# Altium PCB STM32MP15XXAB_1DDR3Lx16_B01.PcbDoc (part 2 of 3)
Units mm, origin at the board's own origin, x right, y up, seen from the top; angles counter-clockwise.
Board outline 86 x 120 mm, 4 copper layers (Top Layer, Signal Layer 1, Signal Layer 2, Bottom Layer), stack 1.571 mm thick; 144 components, 93 nets, 930 pads, 372 vias.
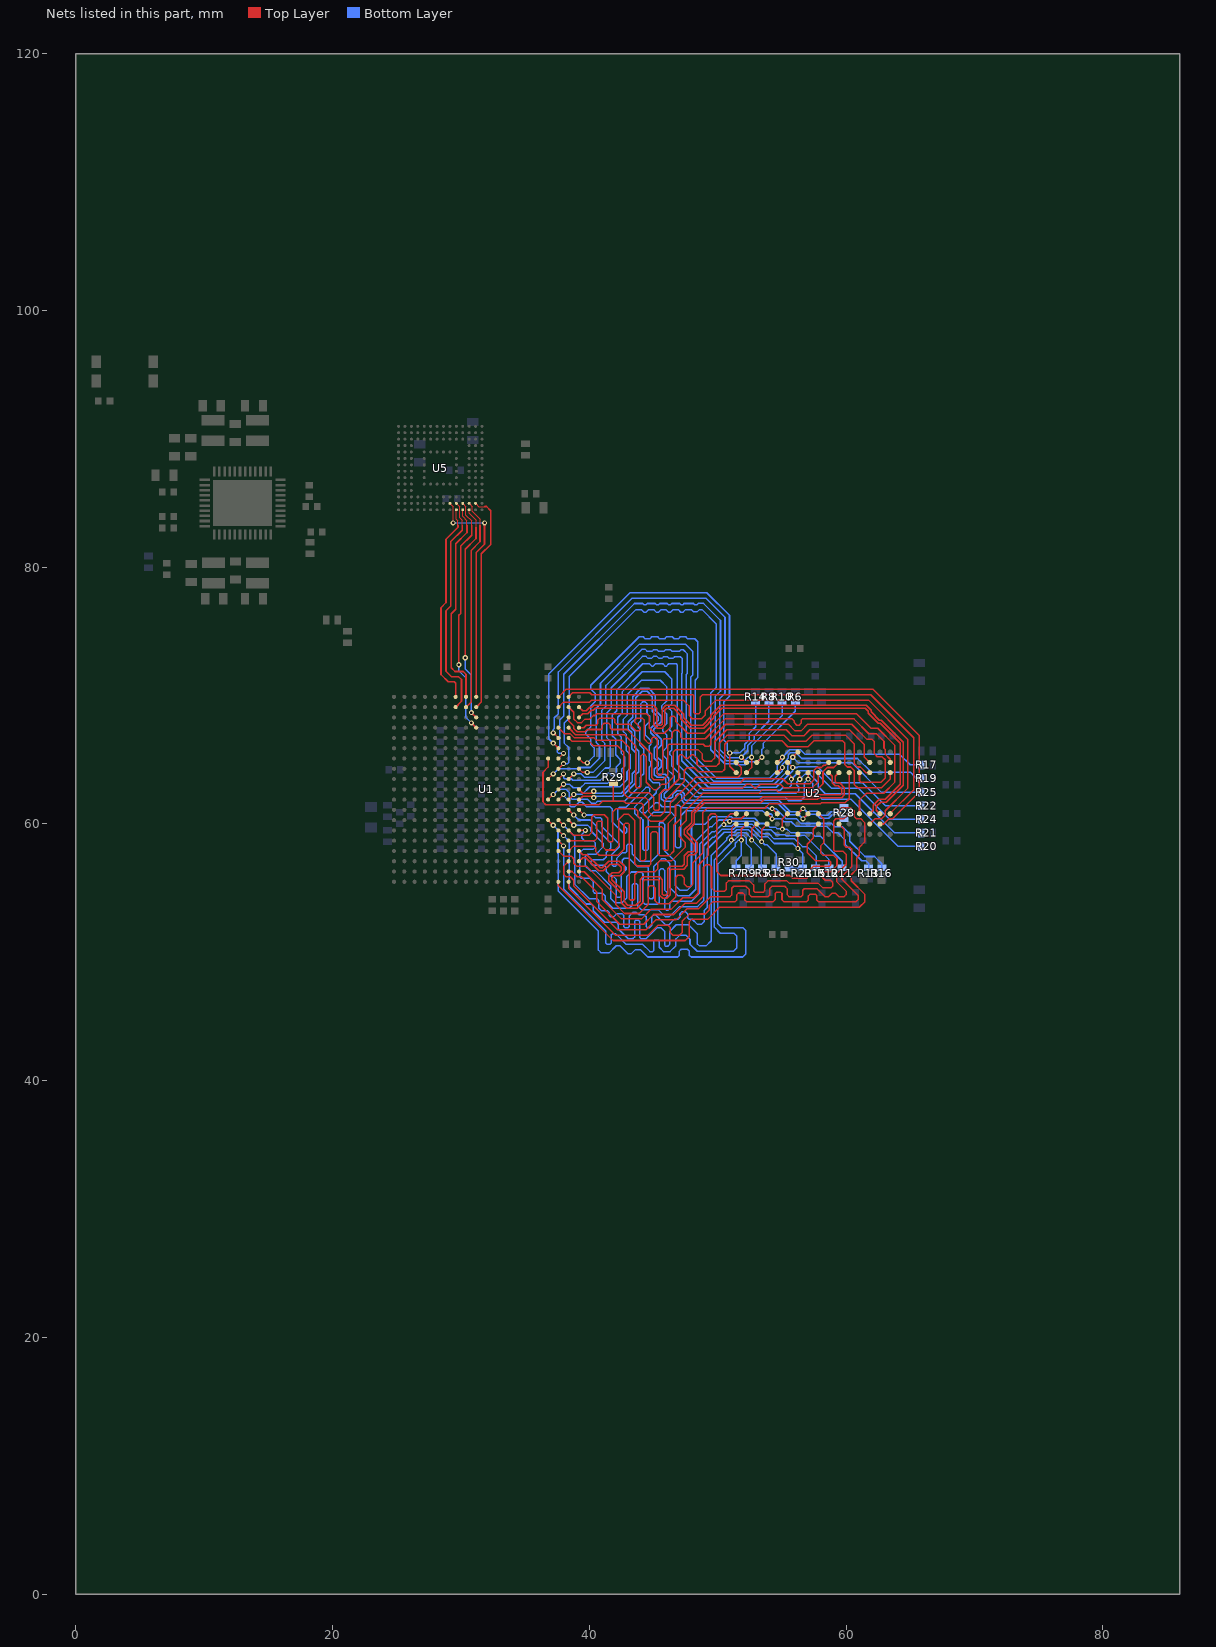
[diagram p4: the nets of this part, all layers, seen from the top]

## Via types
v1: diameter 0.4, hole 0.2, Top Layer to Bottom Layer, tented both sides, 309 vias
v2: diameter 0.6, hole 0.3, Top Layer to Bottom Layer, tented both sides, 61 vias
v3: diameter 0.4, hole 0.2, Top Layer to Signal Layer 1, tented top, 2 vias

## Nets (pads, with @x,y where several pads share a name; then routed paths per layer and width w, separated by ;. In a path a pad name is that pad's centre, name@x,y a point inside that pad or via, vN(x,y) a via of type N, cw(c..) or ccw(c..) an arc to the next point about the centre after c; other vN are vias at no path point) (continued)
DDR_A4: R5.1 U1.P17 U2.P8 | length 39.6
  Top Layer w0.12: U1.P17@37.6,59.5 v1(38,59.1) ; v1(52.65,58.75) 52.65,59.6 U2.P8@53.05,60
  Bottom Layer w0.12: v1(38,59.1) 38.44,58.66 38.44,55.117 39.787,53.77 40.16,53.77 40.32,53.61 40.32,53.237 41.217,52.34 42.13,52.34 42.27,52.2 42.27,51.836 43.046,51.06 43.39,51.06 43.53,51.2 43.53,52.41 43.615,52.495 43.845,52.495 43.95,52.39 43.95,51.16 44.05,51.06 44.43,51.06 45.304,51.934 45.574,51.934 45.869,51.639 45.869,50.571 45.96,50.48 46.12,50.48 46.29,50.65 46.29,51.648 46.786,52.144 47.732,52.144 48.43,51.446 48.43,50.65 48.58,50.5 49.1,50.5 49.5,50.9 49.5,57.55 50.71,58.76 50.71,58.899 50.921,59.11 51.37,59.11 51.59,59.33 52.19,59.33 52.65,58.87 v1(52.65,58.75) 52.679,58.75 53.41,58.019 53.41,56.7 R5.1@53.5,56.61
DDR_A5: R6.1 U1.H17 U2.P2 | length 43.5
  Top Layer w0.12: U1.H17@37.6,64.3 v1(38,64.7) ; U2.P2@53.05,64.8 v1(53.45,65.2)
  Bottom Layer w0.12: v1(38,64.7) 38.3,64.7 38.4,64.8 38.4,65.95 38.04,66.31 38.04,67.843 38.44,68.243 38.44,71.498 43.642,76.7 44.044,76.7 44.259,76.484 44.416,76.484 44.631,76.7 45.019,76.7 45.244,76.475 45.381,76.475 45.606,76.7 45.969,76.7 46.164,76.504 46.346,76.504 46.541,76.7 46.936,76.7 47.136,76.5 47.3,76.5 47.5,76.7 47.954,76.7 48.139,76.514 48.4,76.514 48.586,76.7 48.787,76.7 49.9,75.587 49.9,70.625 49.475,70.2 49.475,65.775 50.56,64.69 51.39,64.69 51.46,64.62 52.15,64.62 52.37,64.84 53.09,64.84 v1(53.45,65.2) 53.45,65.811 53.59,65.951 53.57,65.971 53.57,66.3 56.05,68.78 R6.1@56.05,69.45
DDR_A6: R7.1 U1.N16 U2.R8 | length 40.5
  Top Layer w0.12: U1.N16@36.8,60.3 v1(37.2,59.9) ; v1(51.85,58.75) 51.85,59.6 U2.R8@52.25,60
  Bottom Layer w0.12: v1(37.2,59.9) 37.57,59.53 37.57,57.69 37.6,57.66 37.6,54.769 40.719,51.65 40.719,50.181 40.94,49.96 41.54,49.96 42.099,50.519 42.399,50.519 43.008,49.91 43.29,49.91 43.6,50.22 43.976,50.22 44.556,49.64 45.114,49.64 46.89,49.64 47,49.75 47,50.075 47.175,50.25 47.64,50.25 47.79,50.1 47.79,49.785 47.935,49.64 51.965,49.64 52.2,49.875 52.2,51.7 51.975,51.925 50.335,51.925 50.025,52.235 50.025,56.887 51.088,57.95 51.088,57.957 51.381,58.25 51.381,58.499 51.632,58.75 v1(51.85,58.75) 51.85,57.54 51.45,57.14 R7.1@51.45,56.61
DDR_A7: R8.1 U1.E17 U2.R2 | length 39.6
  Top Layer w0.12: v1(37.2,67.1) U1.E17@37.6,66.7 ; v1(51.85,65.2) U2.R2@52.25,64.8
  Bottom Layer w0.12: v1(37.2,67.1) 37.2,67.35 37.28,67.43 37.28,68.271 37.6,68.591 37.6,71.846 43.352,77.598 49.077,77.598 50.575,76.1 50.575,70.175 50.15,69.75 50.15,65.821 50.801,65.17 51.82,65.17 v1(51.85,65.2) 52.35,65.7 52.35,66.109 52.87,66.629 52.87,66.883 53.99,68.003 R8.1@53.99,69.45
DDR_A8: R9.1 U1.R17 U2.T8 | length 39.7
  Top Layer w0.12: U1.R17@37.6,58.7 v1(38,58.3) ; v1@51.09,58.77 51.09,59.64 U2.T8@51.45,60
  Bottom Layer w0.12: v1(38,58.3) 38.02,58.28 38.02,54.943 41.29,51.673 41.29,50.73 41.39,50.63 41.6,50.63 41.71,50.74 41.71,51.37 41.81,51.47 42.042,51.47 42.872,50.64 44.15,50.64 44.73,50.06 44.94,50.06 45.03,50.15 45.03,50.88 45.1,50.95 45.374,50.95 45.449,50.875 45.449,50.397 45.786,50.06 46.294,50.06 46.753,50.519 46.753,51.053 47.025,51.325 47.55,51.325 47.85,51.025 47.85,50.636 48.406,50.08 51.23,50.08 51.5,50.35 51.5,51.275 51.275,51.5 50.2,51.5 49.75,51.95 49.75,57.213 51.07,58.533 v1(51.07,58.75) ; v1@51.11,58.75 51.321,58.75 51.681,59.11 52.02,59.11 52.22,58.91 52.22,58.48 52.61,58.09 52.61,56.74 R9.1@52.48,56.61
DDR_A9: R10.1 U1.G17 U2.R3 | length 43
  Top Layer w0.12: U1.G17@37.6,65.1 v1(38,65.5) ; U2.R3@52.25,64 52.65,64.4 v1(52.65,65.2)
  Bottom Layer w0.12: v1(38,65.5) 37.625,65.5 37.525,65.6 37.525,65.775 37.7,65.95 37.7,68.097 38.02,68.417 38.02,71.672 43.523,77.175 44.163,77.175 44.263,77.075 44.412,77.075 44.512,77.175 45.138,77.175 45.238,77.075 45.387,77.075 45.487,77.175 46.088,77.175 46.188,77.075 46.322,77.075 46.422,77.175 47.055,77.175 47.155,77.075 47.281,77.075 47.381,77.175 48.125,77.175 48.225,77.075 48.39,77.075 48.493,77.178 48.903,77.178 50.225,75.856 50.225,70.35 49.8,69.925 49.8,65.831 50.701,64.93 51.59,64.93 51.68,64.84 52,64.84 52.36,65.2 v1(52.65,65.2) 52.65,66.069 55.02,68.439 R10.1@55.02,69.45
DDR_A10: R11.1 U1.M19 U2.L7 | length 42.3
  Top Layer w0.12: U1.M19@39.22,61.1 U1.M19@39.2,61.1 v1(39.6,60.7) ; v1(55.05,59.6) 55.05,60.4 U2.L7@55.45,60.8
  Bottom Layer w0.12: v1(39.6,60.7) 40.282,60.7 40.482,60.5 40.875,60.5 40.96,60.415 40.96,59.816 42.34,58.436 42.34,58.2 41.74,57.6 41.74,56.85 41.865,56.725 42.05,56.725 42.15,56.825 42.16,56.825 42.16,57.344 42.56,57.744 42.814,57.744 42.93,57.86 42.93,58.33 43.04,58.44 43.24,58.44 43.35,58.33 43.35,57.673 43.923,57.101 44.848,57.101 45.45,57.703 45.45,60.04 45.5,60.09 45.74,60.09 45.87,59.96 45.87,57.922 46.71,57.082 46.71,55.212 47.094,54.828 47.618,54.828 47.966,55.176 47.966,59.791 48.15,59.975 49.025,59.975 49.61,60.56 50.91,60.56 51.089,60.56 51.199,60.45 52.89,60.45 53.3,60.04 53.79,60.04 54.067,59.763 54.5,59.763 54.62,59.643 55.007,59.643 v1(55.05,59.6) 55.41,59.6 55.68,59.33 57.29,59.33 57.56,59.06 57.999,59.06 58.26,58.799 58.26,58.53 59.7,57.09 R11.1@59.7,56.61
DDR_A11: R12.1 U1.M18 U2.R7 | length 46.6
  Top Layer w0.12: U1.M18@38.4,61.1 v1(38.8,60.7) ; v1@50.94,60.21 51.13,60.4 51.85,60.4 U2.R7@52.25,60.8
  Bottom Layer w0.12: v1(38.8,60.7) 39.19,60.31 40.078,60.31 40.54,59.848 40.54,59.642 41.688,58.494 41.688,58.142 41.32,57.774 41.32,57.43 41.1,57.21 40.25,57.21 40.12,57.08 40.12,56.92 40.25,56.79 41.16,56.79 41.16,56.78 41.31,56.63 41.31,56.316 41.676,55.95 41.85,55.95 42.09,55.71 42.09,54.38 42.19,54.28 42.37,54.28 42.51,54.42 42.51,56.079 42.866,56.434 42.866,56.624 42.58,56.91 42.58,57.17 42.734,57.324 43.105,57.324 43.749,56.681 44.5,56.681 44.61,56.571 44.61,54.29 44.725,54.175 44.915,54.175 45.03,54.29 45.03,56.689 45.625,57.284 45.914,57.284 46.29,56.908 46.29,55.038 46.92,54.408 47.792,54.408 48.3,54.916 48.3,58.675 49.424,59.799 49.569,59.799 50.08,60.31 50.84,60.31 50.94,60.21 52.79,60.21 53.457,59.543 54.177,59.543 54.56,59.16 55.24,59.16 55.32,59.08 56.471,59.08 56.501,59.11 56.799,59.11 58.67,57.239 R12.1@58.67,56.61
  other v1: 50.94,60.2
DDR_A12: R13.1 U1.L17 U2.N7 | length 47.2
  Top Layer w0.12: U1.L17@37.6,61.9 v1(38,62.3) ; U2.N7@53.85,60.8 v1(54.25,60.4)
  Bottom Layer w0.12: v1(38,62.3) 38,62.23 38.49,61.74 38.49,61.42 38.58,61.33 38.85,61.33 39.21,61.69 39.45,61.69 39.81,61.33 41.64,61.33 41.8,61.17 41.8,60.164 42.684,59.28 42.82,59.28 42.93,59.39 42.93,59.646 42.22,60.356 42.22,61.16 42.38,61.32 42.889,61.32 44.419,62.85 44.625,62.85 44.725,62.75 44.725,62.525 43.53,61.33 43.53,60.846 43.906,60.47 44.04,60.47 44.19,60.32 44.19,58.021 44.271,57.941 44.5,57.941 44.61,58.051 44.61,60.516 45.024,60.93 46.37,60.93 46.71,60.59 46.71,58.27 46.84,58.14 47.006,58.14 47.126,58.26 47.126,60.646 47.52,61.04 53.5,61.04 53.76,60.78 54.17,60.78 54.25,60.7 v1(54.25,60.4) 54.931,60.4 55.151,60.18 55.74,60.18 56.1,59.82 58.49,59.82 58.975,59.335 59.355,59.335 59.93,58.76 59.93,58.43 61.22,57.14 61.56,57.14 61.76,56.94 R13.1@61.76,56.61
DDR_A13: R14.1 U1.F17 U2.T3 | length 41.6
  Top Layer w0.12: v1(37.2,66.3) U1.F17@37.6,65.9 ; v1(50.95,65.53) 50.95,64.5 U2.T3@51.45,64
  Bottom Layer w0.12: v1@37.2,66.28 37.19,66.29 36.84,66.64 36.84,71.68 43.178,78.018 49.157,78.018 50.925,76.25 50.925,69.95 50.485,69.51 50.485,66.535 50.74,66.28 50.74,65.74 v1(50.95,65.53) 51.18,65.53 51.21,65.56 51.77,65.56 52.11,65.9 52.11,66.208 52.45,66.548 52.45,67.057 52.97,67.577 R14.1@52.97,69.45
DDR_A14: R15.1 U1.N18 U2.T7 | length 45
  Top Layer w0.12: U1.N18@38.4,60.3 v1(38.8,59.9) ; v1(50.49,59.95) 50.49,60.28 51.01,60.8 U2.T7@51.45,60.8
  Bottom Layer w0.12: v1(38.8,59.9) 38.81,59.89 39.904,59.89 40.12,59.674 40.12,59.468 41.084,58.504 41.084,58.21 40.504,57.63 39.854,57.63 39.7,57.476 39.7,56.746 40.076,56.37 40.48,56.37 41.67,55.18 41.67,54.206 42.016,53.86 42.544,53.86 42.93,54.246 42.93,55.905 43.286,56.261 44.059,56.261 44.19,56.13 44.19,53.9 44.335,53.755 45.325,53.755 45.45,53.88 45.45,56.375 45.575,56.5 45.75,56.5 45.87,56.38 45.87,54.864 46.07,54.664 46.07,54.36 45.87,54.16 45.87,53.42 46.02,53.27 46.13,53.27 46.29,53.43 46.29,53.876 46.402,53.988 47.966,53.988 48.625,54.647 48.625,58.465 49.539,59.379 49.749,59.379 50.32,59.95 v1(50.49,59.95) 50.5,59.95 50.62,59.83 51.089,59.83 51.249,59.99 52.68,59.99 53.43,59.24 53.997,59.24 54.397,58.84 56.009,58.84 56.61,58.239 56.971,58.239 57.67,57.54 57.67,56.64 R15.1@57.64,56.61
DDR_A15: R16.1 U1.L16 U2.M7 | length 48.7
  Top Layer w0.12: U1.L16@36.8,61.9 v1(37.2,62.3) ; v1(54.25,61.2) U2.M7@54.65,60.8
  Bottom Layer w0.12: v1(37.2,62.3) 37.6,62.7 38.19,62.7 38.44,62.45 38.44,62.151 38.651,61.94 39.849,61.94 40.189,61.6 40.48,61.6 40.65,61.77 42.745,61.77 43.994,63.019 43.994,63.651 44.25,63.907 44.25,65.832 43.95,66.132 43.95,67.402 43.81,67.542 43.81,67.825 44.03,68.045 44.03,69.38 44.175,69.525 44.35,69.525 44.5,69.375 44.5,68.62 44.7,68.42 44.7,67.965 44.37,67.635 44.37,66.925 44.81,66.485 44.81,66.22 44.67,66.08 44.67,64.95 44.795,64.825 44.795,64.55 44.67,64.425 44.67,63.52 44.97,63.22 45.419,63.22 45.509,63.13 45.509,62.904 45.22,62.615 45.22,62.426 43.95,61.156 43.95,61.02 44.08,60.89 44.39,60.89 45.16,61.66 45.375,61.66 45.685,61.35 46.635,61.35 46.755,61.47 46.98,61.47 47.17,61.28 53.9,61.28 53.98,61.2 v1(54.25,61.2) 54.52,61.2 55.32,60.4 56.141,60.4 56.501,60.04 58.88,60.04 59.13,59.79 59.73,59.79 60.29,59.23 60.29,58.651 61.471,57.47 62.22,57.47 62.79,56.9 R16.1@62.79,56.61
DDR_BA0: R17.1 U1.G19 U2.M2 | length 47.9
  Top Layer w0.12: U1.G19@39.2,65.1 39.54,64.76 v1(39.85,64.76) ; U2.M2@54.65,64.8 v1(55.05,65.2)
  Bottom Layer w0.12: v1(39.85,64.76) 40.38,65.29 40.38,65.923 40.12,66.183 40.12,66.626 39.72,67.026 39.72,67.147 40.12,67.547 40.12,69.184 40.46,69.524 40.46,70.184 40.12,70.524 40.12,70.802 43.893,74.575 44.209,74.575 44.35,74.434 44.725,74.434 44.866,74.575 45.334,74.575 45.475,74.434 45.875,74.434 46.016,74.575 46.475,74.575 46.616,74.434 46.95,74.434 47.091,74.575 47.51,74.575 47.66,74.425 48.225,74.425 48.45,74.2 48.45,71.4 48.25,71.2 48.25,65.225 49.895,63.58 54.059,63.58 54.64,64.161 54.64,64.551 55.05,64.961 v1(55.05,65.2) 55.27,65.42 55.27,65.44 55.61,65.78 55.63,65.78 55.64,65.79 56.46,65.79 56.83,65.42 64.19,65.42 65,64.61 R17.1@65.85,64.61
DDR_BA1: R18.1 U1.N17 U2.N8 | length 37.7
  Top Layer w0.12: U1.N17@37.6,60.3 v1(38,59.9) ; v1@53.43,58.639 53.43,59.58 U2.N8@53.85,60
  Bottom Layer w0.12: v1(38,59.9) 38.86,59.04 38.86,55.331 40.001,54.19 40.6,54.19 40.74,54.05 40.74,53.451 40.935,53.255 41.433,53.255 41.545,53.143 41.545,52.88 41.665,52.76 41.9,52.76 42.16,53.02 42.55,53.02 42.69,52.88 42.69,52.01 42.79,51.91 43.002,51.91 43.11,52.018 43.11,52.836 43.412,53.138 43.648,53.138 43.871,52.915 44.295,52.915 44.44,52.77 44.44,52.02 44.55,51.91 44.686,51.91 44.86,52.084 44.86,52.755 45.02,52.915 45.187,52.915 45.962,52.14 46.188,52.14 46.612,52.564 46.914,52.564 47.07,52.72 47.07,53.022 47.196,53.148 47.525,53.148 47.675,52.998 47.675,52.689 47.789,52.575 48.025,52.575 48.425,52.175 48.725,52.175 48.975,52.425 48.975,53.275 49.2,53.5 49.2,58.025 50.525,59.35 51.299,59.35 51.499,59.55 52.411,59.55 53.331,58.63 v1(53.43,58.63) 53.67,58.39 53.839,58.39 54.56,57.669 54.56,56.64 R18.1@54.53,56.61
DDR_BA2: R19.1 U1.J16 U2.M3 | length 49.3
  Top Layer w0.12: U1.J16@36.8,63.5 v1(37.2,63.9) v1@37.21,63.91 ; U2.M3@54.65,64 v1@55.03,64.38
  Bottom Layer w0.12: v1(37.2,63.9) 37.6,64.3 39.1,64.3 39.2,64.4 40.084,64.4 40.8,65.116 40.8,66.097 40.54,66.357 40.54,69.01 40.88,69.35 40.88,70.968 43.926,74.014 47.477,74.014 48.075,73.416 48.075,71.625 47.925,71.475 47.925,65.075 49.66,63.34 54.25,63.34 55.05,64.14 v1(55.05,64.4) 55.05,64.65 55.44,65.04 55.44,65.089 55.49,65.139 55.49,65.349 55.701,65.56 56.09,65.56 56.55,65.1 60.9,65.1 61.96,64.04 65.01,64.04 65.48,63.57 R19.1@65.85,63.57
DDR_CASN: R21.1 U1.K17 U2.K3 | length 49.1
  Top Layer w0.12: U1.K17@37.6,62.7 37.61,62.7 v1@38.005,63.095 ; U2.K3@56.25,64 56.25,63.92 56.4,63.77 v1(56.4,63.49)
  Bottom Layer w0.12: v1@38.02,63.08 v1(38,63.1) 38.47,63.1 38.75,62.82 39.33,62.82 39.67,63.16 41.424,63.16 41.594,63.33 42.226,63.33 42.524,63.628 42.524,64.26 42.78,64.516 42.78,65.223 42.48,65.523 42.48,66.793 42.22,67.053 42.22,68.314 42.56,68.654 42.56,70.272 44.138,71.85 45.875,71.85 46.445,71.28 46.445,69.391 46.2,69.146 46.2,69.01 46.445,68.764 46.445,67.631 46.28,67.465 46.28,67.3 46.445,67.134 46.445,65.776 46.28,65.61 46.28,65.42 46.445,65.254 46.445,64.501 47.039,63.908 47.039,63.62 47.15,63.509 47.438,63.509 48.566,62.38 56.1,62.38 56.33,62.61 56.33,62.87 56.17,63.03 56.17,63.21 56.17,63.26 v1(56.4,63.49) 56.77,63.86 57.199,63.86 57.84,63.219 57.84,62.91 58.39,62.36 ; 58.34,62.4 58.38,62.36 58.39,62.36 ; R21.1@65.85,59.31 63.77,59.31 60.72,62.36 58.39,62.36
DDR_CKE: R23.1 R30.2 U1.P19 U2.K9 | length 38.3
  Top Layer w0.12: U1.P19@39.2,59.5 v1(39.7,59.5) ; v1(56.25,58.09) U2.K9@56.25,59.2
  Bottom Layer w0.12: v1(39.7,59.5) 39.7,59.47 39.41,59.18 39.41,58.92 39.64,58.69 40.3,58.69 40.302,58.692 40.48,58.514 40.48,58.2 40.33,58.05 39.56,58.05 39.28,57.77 39.28,55.86 39.37,55.77 40.055,55.77 40.3,55.525 40.3,54.74 40.43,54.61 41.03,54.61 41.25,54.39 41.25,54.032 41.842,53.44 43.12,53.44 43.35,53.67 43.35,55.25 43.45,55.35 43.675,55.35 43.77,55.255 43.77,53.61 44.045,53.335 45.361,53.335 45.936,52.76 46.214,52.76 47.022,53.568 48.444,53.568 48.925,54.049 48.925,58.3 49.6,58.975 49.729,58.975 50.341,59.587 50.341,59.59 51.16,59.59 51.228,59.59 51.408,59.77 52.54,59.77 53.29,59.02 53.88,59.02 54.42,58.48 55.86,58.48 v1(56.25,58.09) 56.64,57.7 56.64,56.64 R23.1@56.61,56.61 56.57,56.57 R30.2@55.57,56.57
DDR_CLK_N: R28.1 U1.K19 U2.K7 | length 40.4
  Top Layer w0.1: U1.K19@39.2,62.7 39.49,62.41 40.21,62.41 v1(40.35,62.55) ; U2.K7@56.25,60.8 v1(56.65,61.2)
  Bottom Layer w0.1: v1(40.35,62.55) 40.49,62.41 42.48,62.41 43.354,63.284 43.354,63.916 43.61,64.172 43.61,65.567 43.31,65.867 43.31,67.137 43.05,67.397 43.05,67.97 43.39,68.31 43.39,69.915 44.031,70.556 44.619,70.556 45.158,70.017 45.158,68.868 45.615,68.41 45.615,67.975 45.01,67.37 45.01,67.19 45.615,66.585 45.615,66.12 45.31,65.815 45.31,65.215 45.615,64.91 45.615,64.455 45.31,64.15 45.31,63.95 45.4,63.86 45.913,63.86 46.209,63.564 46.209,62.699 45.86,62.35 45.86,62.08 45.95,61.99 46.37,61.99 46.52,62.14 46.52,62.305 46.813,62.599 47.174,62.599 47.42,62.353 47.42,61.935 47.505,61.85 54.775,61.85 55.665,60.96 56.41,60.96 v1(56.65,61.2) 56.7,61.2 56.94,60.96 57.145,60.96 57.175,60.99 57.755,60.99 58.075,60.67 58.56,60.67 58.86,60.97 59.5,60.97 R28.1@59.85,61.32
DDR_CLK_P: R28.2 U1.L19 U2.J7 | length 40.4
  Top Layer w0.1: U1.L19@39.2,61.9 39.48,62.18 40.22,62.18 v1(40.35,62.05) ; v1(56.65,60.4) U2.J7@57.05,60.8
  Bottom Layer w0.1: v1(40.35,62.05) 40.48,62.18 42.575,62.18 43.584,63.189 43.584,63.821 43.84,64.077 43.84,65.662 43.54,65.962 43.54,67.232 43.28,67.492 43.28,67.875 43.62,68.215 43.62,69.82 44.126,70.326 44.524,70.326 44.928,69.922 44.928,68.772 45.385,68.315 45.385,68.07 44.78,67.465 44.78,67.095 45.385,66.49 45.385,66.215 45.08,65.91 45.08,65.12 45.385,64.815 45.385,64.55 45.08,64.245 45.08,63.855 45.305,63.63 45.817,63.63 45.979,63.469 45.979,62.794 45.63,62.445 45.63,61.985 45.855,61.76 46.465,61.76 46.75,62.045 46.75,62.21 46.909,62.369 47.079,62.369 47.19,62.257 47.19,61.84 47.41,61.62 54.68,61.62 55.57,60.73 56.317,60.73 v1@56.605,60.443 ; v1(56.65,60.4) 56.98,60.73 57.24,60.73 57.27,60.76 57.66,60.76 57.98,60.44 58.655,60.44 58.955,60.74 59.53,60.74 R28.2@59.85,60.42
DDR_CSN: R22.1 U1.J18 U2.L2 | length 47.3
  Top Layer w0.12: U1.J18@38.4,63.5 v1(38.8,63.9) ; U2.L2@55.45,64.8 v1(55.85,64.4)
  Bottom Layer w0.12: v1(38.8,63.9) 39.389,63.9 39.639,63.65 40.522,63.65 41.232,64.36 41.535,64.36 41.64,64.465 41.64,66.445 41.38,66.705 41.38,68.662 41.72,69.002 41.72,70.62 44.15,73.05 44.425,73.05 44.425,73.045 44.575,72.895 44.845,72.895 45,73.05 45.275,73.05 45.43,72.895 45.67,72.895 45.813,73.038 46.082,73.038 46.225,72.895 46.52,72.895 46.66,73.035 47.095,73.035 47.25,72.88 47.25,71.775 47.2,71.725 47.2,64.934 49.274,62.86 54.57,62.86 55.85,64.14 v1(55.85,64.4) 56.197,64.4 56.257,64.46 57.787,64.46 59.047,63.2 61.3,63.2 63.07,61.43 R22.1@65.85,61.43
DDR_DQ0: U1.A17 U2.B8 | length 38.3
  Top Layer w0.12: U1.A17@37.6,69.9 38.19,70.49 62.112,70.49 65.7,66.902 65.7,62.487 63.618,60.405 63.345,60.405 62.94,60 U2.B8@62.65,60
DDR_DQ1: U1.A18 U2.A7 | length 37.8
  Top Layer w0.12: U1.A18@38.4,69.9 38.4,69.92 38.7,70.22 40.041,70.22 40.191,70.07 48.08,70.07 48.15,70 48.15,68.675 48.225,68.6 48.55,68.6 48.65,68.7 48.65,69.9 48.82,70.07 61.93,70.07 65.275,66.725 65.275,62.656 U2.A7@63.47,60.851
DDR_DQ2: U1.D18 U2.C2 | length 38.9
  Top Layer w0.12: U1.D18@38.4,67.5 38.96,66.94 42.768,66.94 43.61,66.098 43.61,62.915 43.7,62.825 43.925,62.825 44.03,62.93 44.03,65.304 44.15,65.424 44.284,65.424 44.45,65.258 44.45,63.244 45.044,62.65 45.21,62.65 45.64,63.08 45.978,63.08 46.55,63.652 46.55,65.61 46.74,65.8 48.47,65.8 48.814,65.456 48.814,65.05 48.964,64.9 49.525,64.9 49.775,65.15 49.775,66.4 50.715,67.34 55.339,67.34 55.819,66.86 56.701,66.86 57.181,67.34 60.279,67.34 61.41,66.209 61.41,65.24 U2.C2@61.85,64.8
DDR_DQ3: U1.B17 U2.C8 | length 38.6
  Top Layer w0.12: U1.B17@37.6,69.1 38,69.5 40.041,69.5 40.191,69.65 47.325,69.65 47.78,69.195 47.78,68.445 48.025,68.2 48.75,68.2 49.05,68.5 49.05,68.825 49.875,69.65 61.75,69.65 64.8,66.6 64.8,62.775 63.05,61.025 63.05,60.691 62.759,60.4 62.25,60.4 U2.C8@61.85,60
DDR_DQ4: U1.E18 U2.A3 | length 39
  Top Layer w0.12: U1.E18@38.4,66.7 38.64,66.46 39.974,66.46 40.334,66.1 42.2,66.1 42.69,65.61 42.69,62.374 43.034,62.03 44.416,62.03 44.62,61.826 44.62,60.976 44.956,60.64 45.554,60.64 45.88,60.966 45.88,61.794 47.4,63.314 47.4,64.15 47.625,64.375 48.175,64.375 48.49,64.06 50.34,64.06 50.55,64.27 50.55,66.21 50.82,66.48 55.011,66.48 55.471,66.02 57.049,66.02 57.509,66.48 59.73,66.48 59.89,66.32 59.89,64.651 60.101,64.44 60.37,64.44 60.65,64.16 60.65,63.08 60.91,62.82 62.766,62.82 63.45,63.504 U2.A3@63.45,64
DDR_DQ5: U1.D17 U2.C3 | length 38.2
  Top Layer w0.12: U1.D17@37.6,67.5 38.06,67.04 38.513,67.04 38.853,66.7 40.38,66.7 40.56,66.52 42.555,66.52 43.11,65.965 43.11,62.548 43.208,62.45 44.63,62.45 45.04,62.04 45.04,61.15 45.13,61.06 45.38,61.06 45.46,61.14 45.46,62.306 45.814,62.66 46.152,62.66 46.97,63.478 46.97,65.28 47.07,65.38 47.26,65.38 47.52,65.12 47.69,65.12 47.95,65.38 48.148,65.38 48.394,65.134 48.394,64.67 48.584,64.48 49.87,64.48 50.12,64.73 50.12,66.295 50.725,66.9 55.185,66.9 55.645,66.44 56.875,66.44 57.335,66.9 59.99,66.9 60.65,66.24 60.65,64.691 60.901,64.44 61.119,64.44 61.559,64 U2.C3@61.85,64
DDR_DQ6: U1.D19 U2.A2 | length 38.5
  Top Layer w0.12: U1.D19@39.2,67.5 39.57,67.5 39.77,67.7 40.55,67.7 40.675,67.825 40.675,68.1 40.825,68.25 41.875,68.25 42,68.125 42,67.9 42.125,67.775 43.134,67.775 43.65,67.259 43.884,67.259 43.975,67.35 43.975,67.525 43.55,67.95 43.55,68.1 43.675,68.225 44.15,68.225 44.3,68.075 44.3,66.6 44.625,66.275 44.775,66.275 44.875,66.375 44.875,66.65 44.975,66.75 45.2,66.75 45.29,66.66 45.29,63.935 45.425,63.8 45.575,63.8 45.71,63.935 45.71,66.51 45.84,66.64 46.34,66.64 46.457,66.757 46.457,67.107 46.65,67.3 46.9,67.3 47.12,67.08 47.12,66.78 47.26,66.64 49.04,66.64 50.58,68.18 55.82,68.18 55.97,68.03 55.97,67.897 56.167,67.7 56.353,67.7 56.5,67.847 56.5,68.08 56.6,68.18 60.628,68.18 61.778,67.03 62.37,67.03 62.96,66.44 62.96,65.89 63.04,65.81 63.04,65.46 63.45,65.05 U2.A2@63.45,64.8
DDR_DQ7: U1.B18 U2.D7 | length 38.3
  Top Layer w0.12: U1.B18@38.4,69.1 38.8,68.7 38.8,68.18 39.08,67.9 39.4,67.9 39.67,68.17 40.045,68.17 40.325,68.45 40.476,68.45 40.626,68.6 44.44,68.6 44.675,68.365 44.675,67.505 45.12,67.06 45.85,67.06 46.31,67.52 46.31,68.285 46.425,68.4 46.6,68.4 46.73,68.27 46.73,68.011 47.681,67.06 48.96,67.06 50.5,68.6 60.802,68.6 61.952,67.45 62.479,67.45 63.81,66.119 63.81,63.27 62.94,62.4 61.59,62.4 61.05,61.86 U2.D7@61.05,60.8
DDR_DQ8: U1.P18 U2.G2 | length 39.3
  Top Layer w0.12: U1.P18@38.4,59.5 38.79,59.11 39.96,59.11 40.18,59.33 40.18,60.53 40.375,60.725 41.175,60.725 41.45,60.45 41.45,58.725 41.55,58.625 41.775,58.625 41.85,58.7 41.85,60.95 42.09,61.19 43.61,61.19 43.78,61.02 43.78,60.628 43.97,60.438 43.97,57.22 44.04,57.15 44.28,57.15 44.39,57.26 44.39,59.67 44.52,59.8 45.62,59.8 45.75,59.67 45.75,58.07 45.86,57.96 46.07,57.96 46.17,58.06 46.17,60.068 46.72,60.618 46.72,61.446 48.494,63.22 51.773,63.22 52.073,63.52 55.08,63.52 55.47,63.13 57.189,63.13 57.49,63.431 57.49,64.16 57.73,64.4 58.09,64.4 58.26,64.57 58.4,64.57 58.63,64.8 U2.G2@58.65,64.8
DDR_DQ9: U1.T17 U2.E3 | length 38.3
  Top Layer w0.12: U1.T17@37.6,57.9 38,57.5 38.6,57.5 38.8,57.3 38.8,56.94 39.04,56.7 39.82,56.7 42.08,54.44 42.08,53.705 42.755,53.03 43.895,53.03 44.6,53.735 44.6,55.06 44.72,55.18 44.995,55.18 45.125,55.05 45.125,54.025 45.357,53.793 46.228,53.793 46.74,54.305 46.74,55.84 46.9,56 47.2,56 47.4,55.8 47.4,55.325 47.6,55.125 47.875,55.125 48.075,55.325 48.075,56.985 48.84,57.75 48.84,60.893 49.167,61.22 53.67,61.22 54.01,61.56 58.005,61.56 58.095,61.65 59.925,61.65 60.25,61.975 U2.E3@60.25,64
DDR_DQ10: U1.R18 U2.H3 | length 38.3
  Top Layer w0.12: U1.R18@38.4,58.7 40.42,58.7 40.6,58.88 40.6,60.15 40.675,60.225 40.95,60.225 41.03,60.145 41.03,58.245 41.3,57.975 41.975,57.975 42.29,58.29 42.29,60.326 42.734,60.77 43.044,60.77 43.55,60.264 43.55,56.91 43.73,56.73 44.66,56.73 44.81,56.88 44.81,59.286 44.904,59.38 45.23,59.38 45.33,59.28 45.33,57.71 45.5,57.54 46.244,57.54 46.59,57.886 46.59,59.894 47.14,60.444 47.14,61.272 48.668,62.8 51.947,62.8 52.247,63.1 52.56,63.1 52.86,62.8 53.016,62.8 53.316,63.1 54.906,63.1 55.196,62.81 57.361,62.81 57.85,63.299 U2.H3@57.85,64
DDR_DQ11: U1.V19 U2.H8 | length 38.3
  Top Layer w0.12: U1.V19@39.2,56.28 39.62,56.28 41.025,54.875 41.025,54.1 42.515,52.61 44.069,52.61 44.832,53.373 46.402,53.373 47.279,54.25 48.15,54.25 48.5,54.6 48.5,56.79 49.26,57.55 49.26,60.546 49.514,60.8 49.775,60.8 49.92,60.655 49.92,56.318 50.248,55.99 55.599,55.99 55.799,55.79 56.97,55.79 57.22,56.04 57.22,56.47 57.46,56.71 58.71,56.71 58.812,56.812 58.812,57.025 58.702,57.136 57.614,57.136 56.98,57.77 56.98,58.43 57.45,58.9 57.45,59.6 U2.H8@57.85,60
DDR_DQ12: U1.W18 U2.F8 | length 37.7
  Top Layer w0.12: U1.W18@38.4,55.5 38.4,54.977 42.027,51.35 44.591,51.35 45.353,52.113 46.137,52.113 46.3,51.95 46.3,51.563 46.513,51.35 47.05,51.35 47.25,51.55 47.25,52.439 47.801,52.99 49.036,52.99 49.335,53.29 49.335,53.66 49.605,53.93 51.35,53.93 51.475,54.055 51.475,54.475 51.625,54.625 51.975,54.625 52.125,54.475 52.125,54.075 52.27,53.93 54.31,53.93 54.474,54.094 54.474,54.574 54.6,54.7 54.9,54.7 55.014,54.586 55.014,54.096 55.18,53.93 56.9,53.93 57.075,54.105 57.075,54.4 57.205,54.53 57.62,54.53 57.726,54.424 57.726,54.074 57.87,53.93 60.766,53.93 60.94,54.104 60.94,54.444 59.69,55.694 59.69,55.93 60.43,56.67 60.43,58.06 60.295,58.195 60.015,58.195 59.85,58.36 59.85,59.6 U2.F8@59.45,60
DDR_DQ13: U1.T18 U2.F2 | length 38.3
  Top Layer w0.12: U1.T18@38.4,57.9 38.78,58.28 40.36,58.28 40.525,58.115 40.525,57.825 40.775,57.575 42.25,57.575 42.71,58.035 42.71,59.96 42.825,60.075 43.025,60.075 43.13,59.97 43.13,54.14 43.19,54.08 43.46,54.08 43.55,54.17 43.55,56.04 43.8,56.29 45.125,56.29 45.35,56.515 45.35,56.975 45.495,57.12 46.418,57.12 47.47,58.172 47.47,58.58 47.01,59.04 47.01,59.72 47.56,60.27 47.56,61.098 48.842,62.38 53.19,62.38 53.49,62.68 54.54,62.68 54.73,62.49 57.57,62.49 58.21,63.13 58.21,64.069 58.541,64.4 59.05,64.4 U2.F2@59.45,64.8
DDR_DQ14: U1.V18 U2.H7 | length 38.3
  Top Layer w0.12: U1.V18@38.4,56.3 38.66,56.3 39.06,55.9 39.406,55.9 40.596,54.71 40.596,53.969 42.375,52.19 44.243,52.19 45.005,52.953 46.576,52.953 47.453,53.83 48.355,53.83 48.9,54.375 48.9,56.625 49.1,56.825 49.375,56.825 49.525,56.675 49.525,55.025 49.8,54.75 50.525,54.75 50.675,54.9 50.675,55.395 50.85,55.57 52.48,55.57 52.8,55.25 52.8,54.8 52.9,54.7 53.575,54.7 53.675,54.8 53.675,55.32 53.925,55.57 55.403,55.57 55.603,55.37 57.855,55.37 58.2,55.025 58.825,55.025 58.975,55.175 58.975,55.45 58.8,55.625 58.375,55.625 58.15,55.85 58.15,56.175 58.265,56.29 58.814,56.29 59.3,56.776 59.3,57.3 59.044,57.556 58.2,57.556 58.02,57.736 58.02,58.29 58.25,58.52 58.25,60.4 U2.H7@57.85,60.8
DDR_DQ15: U1.W17 U2.F7 | length 38
  Top Layer w0.12: U1.W17@37.6,55.5 37.6,55.183 41.858,50.925 47.475,50.925 47.775,51.225 47.775,52.37 47.975,52.57 49.21,52.57 50.15,53.51 61.04,53.51 61.47,53.94 61.47,54.508 60.4,55.578 60.4,56.04 60.85,56.49 60.85,57.38 61.03,57.56 61.03,58.17 61.45,58.59 61.45,60.109 61.159,60.4 60.81,60.4 60.652,60.558 60.652,60.992 60.394,61.25 59.64,61.25 59.45,61.06 U2.F7@59.45,60.8
DDR_DQM0: U1.C18 U2.D3 | length 38.7
  Top Layer w0.12: U1.C18@38.4,68.3 38.4,68.03 38.8,67.63 38.8,67.447 39.067,67.18 39.67,67.18 39.85,67.36 40.935,67.36 41,67.425 41,67.675 41.175,67.85 41.5,67.85 41.65,67.7 41.65,67.46 41.75,67.36 42.942,67.36 44.87,65.432 44.87,63.63 45.05,63.45 45.754,63.45 46.13,63.826 46.13,66.13 46.22,66.22 48.875,66.22 49.045,66.05 49.325,66.05 49.475,66.2 49.475,66.6 50.635,67.76 55.513,67.76 55.993,67.28 56.527,67.28 57.007,67.76 60.454,67.76 61.604,66.61 62.01,66.61 62.21,66.41 62.21,65.46 62.43,65.24 62.812,65.24 63.05,65.002 63.05,63.575 62.715,63.24 61.185,63.24 61.05,63.375 U2.D3@61.05,64
DDR_DQM1: U1.U18 U2.E7 | length 38.3
  Top Layer w0.12: U1.U18@38.4,57.1 38,56.7 38,56.09 38.19,55.9 38.52,55.9 38.8,55.62 38.8,55.171 42.201,51.77 44.417,51.77 45.179,52.533 46.75,52.533 47.627,53.41 48.535,53.41 49.475,54.35 50.975,54.35 51.1,54.475 51.1,55 51.25,55.15 52.2,55.15 52.475,54.875 52.475,54.5 52.625,54.35 53.939,54.35 54.054,54.466 54.054,54.974 54.23,55.15 55.229,55.15 55.434,54.944 55.434,54.476 55.56,54.35 56.506,54.35 56.633,54.477 56.633,54.833 56.75,54.95 57.736,54.95 58.336,54.35 58.65,54.35 58.9,54.6 59.19,54.6 59.44,54.35 59.856,54.35 60.01,54.504 60.01,54.78 59.27,55.52 59.27,56.104 60.025,56.859 60.025,57.63 59.79,57.865 59.16,57.865 59.05,57.975 59.05,58.379 59.05,60.24 59.21,60.4 59.85,60.4 U2.E7@60.25,60.8
DDR_DQS0_N: U1.B19 U2.B7 | length 37.8
  Top Layer w0.1: U1.B19@39.2,69.09 39.48,68.81 39.78,68.81 40.06,69.09 40.211,69.09 40.361,69.24 45.01,69.24 45.27,68.98 45.27,67.815 45.385,67.7 45.585,67.7 45.67,67.785 45.67,68.955 45.955,69.24 46.665,69.24 47.37,68.535 47.37,68.276 47.946,67.7 48.824,67.7 49.475,68.351 49.475,68.48 50.235,69.24 61.594,69.24 61.969,68.865 61.969,68.725 62.604,68.09 62.744,68.09 64.45,66.384 64.45,63.005 63.145,61.7 62.7,61.7 62.37,61.37 62.37,61.08 U2.B7@62.65,60.8
DDR_DQS0_P: U1.C19 U2.C7 | length 37.4
  Top Layer w0.1: U1.C19@39.2,68.3 39.48,68.58 39.875,68.58 40.155,68.86 40.306,68.86 40.456,69.01 44.915,69.01 45.04,68.885 45.04,67.72 45.29,67.47 45.68,67.47 45.9,67.69 45.9,68.86 46.05,69.01 46.57,69.01 47.14,68.44 47.14,68.181 47.851,67.47 48.919,67.47 49.705,68.256 49.705,68.385 50.33,69.01 61.499,69.01 61.739,68.77 61.739,68.63 62.509,67.86 62.649,67.86 64.22,66.289 64.22,63.1 63.05,61.93 62.605,61.93 62.14,61.465 62.14,61.09 U2.C7@61.85,60.8
DDR_DQS1_N: U1.T19 U2.G3 | length 38
  Top Layer w0.1: U1.T19@39.2,57.9 39.49,57.61 39.815,57.61 40.845,56.58 41.005,56.58 41.53,57.105 42.345,57.105 42.72,56.73 42.72,56.295 42.4,55.975 41.9,55.975 41.75,55.825 41.75,55.675 42.72,54.705 42.72,53.97 43.02,53.67 43.63,53.67 43.96,54 43.96,55.655 44.185,55.88 45.485,55.88 45.7,55.665 45.7,54.545 45.813,54.433 45.963,54.433 46.1,54.57 46.1,56.505 46.305,56.71 47.26,56.71 47.42,56.87 47.42,57.542 47.715,57.837 48.092,57.837 48.19,57.935 48.19,58.44 47.42,59.21 47.42,59.55 47.97,60.1 47.97,60.928 48.912,61.87 53.275,61.87 53.545,62.14 ; 53.547,62.143 53.545,62.14 ; U2.G3@58.685,63.965 58.94,63.71 58.94,63.21 59.175,62.975 59.4,62.975 59.65,62.725 59.65,62.375 59.555,62.28 57.82,62.28 57.68,62.14 53.545,62.14
DDR_DQS1_P: U1.U19 U2.F3 | length 38.4
  Top Layer w0.1: U1.U19@39.2,57.1 39.48,57.38 39.72,57.38 40.75,56.35 41.1,56.35 41.625,56.875 42.25,56.875 42.49,56.635 42.49,56.39 42.305,56.205 41.805,56.205 41.52,55.92 41.52,55.58 41.587,55.512 42.23,54.87 42.49,54.61 42.49,53.875 42.925,53.44 43.725,53.44 44.19,53.905 44.19,55.56 44.28,55.65 45.39,55.65 45.47,55.57 45.47,54.45 45.717,54.203 46.058,54.203 46.33,54.475 46.33,56.41 46.4,56.48 47.355,56.48 47.65,56.775 47.65,57.447 47.81,57.607 48.187,57.607 48.42,57.84 48.42,58.535 47.65,59.305 47.65,59.455 48.2,60.005 48.2,60.833 49.007,61.64 53.37,61.64 53.64,61.91 57.775,61.91 57.915,62.05 59.65,62.05 59.88,62.28 59.88,62.82 59.495,63.205 59.27,63.205 59.17,63.305 59.17,63.72 U2.F3@59.45,64
DDR_ODT: R25.1 U1.H19 U2.K1 | length 46.8
  Top Layer w0.12: U1.H19@39.2,64.3 39.48,64.02 v1(39.85,64.02) ; v1(55.85,65.2) U2.K1@56.25,65.6
  Bottom Layer w0.12: v1(39.85,64.02) 40.298,64.02 41.22,64.942 41.22,66.271 40.96,66.531 40.96,68.836 41.3,69.176 41.3,70.794 44.1,73.594 44.376,73.594 44.5,73.47 44.599,73.47 44.925,73.47 45.03,73.575 45.275,73.575 45.38,73.47 45.845,73.47 45.95,73.575 46.325,73.575 46.445,73.455 47.025,73.455 47.145,73.575 47.323,73.575 47.65,73.247 47.65,71.725 47.575,71.65 47.575,65.003 49.478,63.1 54.42,63.1 55.45,64.13 55.45,64.509 55.7,64.759 55.7,64.98 ; 55.696,64.984 55.85,65.139 v1(55.85,65.2) 56.27,64.78 60.44,64.78 62.73,62.49 R25.1@65.85,62.49
DDR_RASN: R20.1 U1.L18 U2.J3 | length 48.7
  Top Layer w0.12: U1.L18@38.4,61.9 v1(38.8,62.3) ; v1(57.05,63.5) U2.J3@57.05,64
  Bottom Layer w0.12: v1(38.8,62.3) 39.431,62.3 40.041,62.91 42.4,62.91 42.944,63.454 42.944,64.086 43.2,64.342 43.2,65.397 42.9,65.697 42.9,66.967 42.64,67.227 42.64,68.14 42.98,68.48 42.98,70.098 44.082,71.2 45.525,71.2 46.025,70.7 46.025,69.565 45.64,69.18 45.64,68.965 46.025,68.58 46.025,67.805 45.733,67.512 45.733,67.253 46.025,66.96 46.025,65.95 45.768,65.692 45.768,65.338 46.025,65.08 46.025,64.327 46.619,63.734 46.619,63.201 46.731,63.089 47.264,63.089 48.212,62.14 55.203,62.14 55.533,61.81 56.48,61.81 56.75,62.08 56.75,63.2 v1(57.05,63.5) 57.395,63.155 57.395,62.675 58.13,61.94 60.376,61.94 64.066,58.25 R20.1@65.85,58.25
DDR_RESETN: R29.2 U1.G16 U2.T2 | length 24.8
  Top Layer w0.12: U1.G16@36.8,65.1 36.8,64.43 36.4,64.03 36.4,61.72 36.62,61.5 40.76,61.5 41.035,61.775 41.865,61.775 ; R29.2@41.875,63.2 41.865,63.19 41.865,61.775 ; U2.T2@51.45,64.8 51.85,64.4 51.85,63.891 51.599,63.64 48.32,63.64 46.3,61.62 46.3,60.792 45.728,60.22 44.782,60.22 44.2,60.802 44.2,61.48 44.07,61.61 42.86,61.61 42.695,61.775 41.865,61.775
DDR_WEN: R24.1 U1.J17 U2.L3 | length 49
  Top Layer w0.12: U1.J17@37.6,63.5 v1(38,63.9) ; U2.L3@55.45,64 55.75,63.7 v1(55.75,63.5)
  Bottom Layer w0.12: v1(38,63.9) 38,63.6 38.08,63.52 38.586,63.52 ; 38.593,63.527 38.71,63.41 40.876,63.41 41.406,63.94 41.58,63.94 41.77,63.75 41.99,63.75 42.104,63.864 42.104,64.434 42.4,64.73 42.4,65.05 42.06,65.39 42.06,66.619 41.8,66.879 41.8,68.488 42.14,68.828 42.14,70.446 44.169,72.475 44.695,72.475 44.87,72.3 44.98,72.3 45.155,72.475 45.725,72.475 45.9,72.3 46.025,72.3 46.2,72.475 46.775,72.475 46.865,72.385 46.865,64.675 48.92,62.62 54.87,62.62 55.074,62.824 55.554,62.824 55.75,63.02 v1(55.75,63.5) ; v1@55.77,63.52 56.39,64.14 57.513,64.14 58.873,62.78 60.98,62.78 63.39,60.37 R24.1@65.85,60.37
eMMC_SDIO2_D0: U1.C9 U5.A3 | length 17.1
  Top Layer w0.09: U5.A3@30.65,84.475 30.65,84.2 31.188,83.662 31.188,83.087
  Top Layer w0.13: v1(30.35,72.95) 30.35,81.4 31.188,82.238 31.188,83.087 ; v1(30.825,68.675) U1.C9@31.2,68.3
  Bottom Layer w0.13: v1(30.35,72.95) 30.35,72.075 30.825,71.6 v1(30.825,68.675)
eMMC_SDIO2_D1: U1.A8 U5.A4 | length 16.1
  Top Layer w0.09: U5.A4@30.15,84.475 30.15,83.95 30.475,83.625 30.475,83.25
  Top Layer w0.13: U1.A8@30.4,69.9 30.4,71.675 30.2,71.875 29.55,71.875 29.25,72.175 29.25,76.375 29.6,76.725 29.6,81.825 30.475,82.7 30.475,83.25
eMMC_SDIO2_D2: U1.A7 U5.A5 | length 15.9
  Top Layer w0.09: U5.A5@29.65,84.475 29.65,83.725 29.775,83.6 29.775,83.25
  Top Layer w0.13: U1.A7@29.6,69.9 29.6,70.975 29.5,71.075 29.025,71.075 28.45,71.65 28.45,76.85 28.85,77.25 28.85,82.175 29.775,83.1 29.775,83.25
eMMC_SDIO2_D3: U1.B9 U5.B2 | length 17.2
  Top Layer w0.09: U5.B2@31.15,84.975 31.4,84.725 31.875,84.725
  Top Layer w0.13: U1.B9@31.2,69.1 31.6,69.5 31.6,81.05 32.325,81.775 32.325,84.4 32,84.725 31.875,84.725
eMMC_SDIO2_D4: U1.B8 U5.B3 | length 16.7
  Top Layer w0.09: U5.B3@30.65,84.975 30.65,84.965 30.9,84.715 30.9,84.35 31.5,83.75 31.5,83.275
  Top Layer w0.13: U1.B8@30.4,69.1 30.8,69.5 30.8,81.3 31.5,82 31.5,83.275
eMMC_SDIO2_D5: U1.D9 U5.B4 | length 18.7
  Top Layer w0.09: U5.B4@30.15,84.975 30.4,84.725 30.4,84.05 30.85,83.6 30.85,83.25
  Top Layer w0.13: v1(29.85,72.4) 29.85,76.25 30,76.4 30,81.65 30.85,82.5 30.85,83.25 ; v1(30.825,67.875) U1.D9@31.2,67.5
  Bottom Layer w0.12: v1(29.85,72.4) 29.85,71.925 30.375,71.4 30.375,68.325 v1(30.825,67.875)
eMMC_SDIO2_D6: U1.B7 U5.B5 | length 17.6
  Top Layer w0.09: U5.B5@29.65,84.975 29.65,84.965 29.9,84.715 29.9,83.85 30.1,83.65 30.1,83.25
  Top Layer w0.13: U1.B7@29.6,69.1 30.05,69.55 30.05,71.25 29.825,71.475 29.275,71.475 28.85,71.9 28.85,76.6 29.225,76.975 29.225,82 30.1,82.875 30.1,83.25
eMMC_SDIO2_D7: U1.A9 U5.B6 | length 17.9
  Top Layer w0.09: U5.B6@29.15,84.975 29.4,84.725 v1(29.4,83.45)
  Top Layer w0.13: U1.A9@31.2,69.9 31.2,81.15 31.85,81.8 v1(31.85,83.45)
  Bottom Layer w0.09: v1(29.4,83.45) v1(31.85,83.45)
